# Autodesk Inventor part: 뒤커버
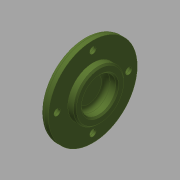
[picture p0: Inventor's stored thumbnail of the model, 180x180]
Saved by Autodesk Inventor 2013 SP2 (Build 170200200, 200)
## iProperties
Created: 2015-12
Part Number: 뒤커버
Document SubType Name: Modeling
Designer: mdu
Density: 2.71 g/cm^3
Material: 알루미늄 6061
Author: mdu
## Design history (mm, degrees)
sketch "스케치1"
  geometry: L1 (-7, 0)-(7, 0); L2 (-7, 0)-(-7, 15.539); L3 (-7, 15.539)-(-4, 18.5); L4 (-4, 18.5)-(-4, 31); L5 (-4, 31)-(2, 31); L6 (2, 31)-(2, 17.5); L7 (2, 17.5)-(7, 17.5); L8 (7, 17.5)-(7, 0); 2 further points
  constraints: 16 end point, 4 parallel, 2 perpendicular, 1 coincident, 1 horizontal, 1 midpoint
  dimensions: "d0" = 14 distance of L1.start L1.end; "d1" = 62 diameter of L5 L1; "d2" = 35 diameter of L7 L1; "d3" = 37 diameter of L3.end L1; "d4" = 3 distance between parallel lines of L4 L2; "d5" = 6 distance of L4.end L5.end
revolve "회전1" sketch "스케치1" stored, may be unused: angle "d6" = 90 deg
sketch "스케치2" dims "d32" = 50
  geometry: 3 further points
  constraints: 2 vertical alignment, 1 coincident, 2 other
hole "구멍1" sketch "스케치2" at (0, 25) diameter "d8" = 4.5; stored, may be unused: countersink angle "d12" = 90 deg, drill point angle "d14" = 118 deg; dims "d9" = 6, "d10" = 8, "d11" = 4.4, "d13" = 8
hole "구멍2" diameter "d20" = 24; stored, may be unused: countersink angle "d24" = 90 deg, drill point angle "d26" = 0 deg; dims "d18" = 10, "d19" = 10, "d21" = 6, "d22" = 8, "d23" = 4.4, "d25" = 8
fillet "모깎기1" dims "d27" = 3
fillet "모깎기2" dims "d28" = 3
chamfer "모따기1" distance "d29" = 1; stored, may be unused: second distance "d30" = 2, angle "d31" = 45 deg
node "솔리드1"
pattern_circular "원형 패턴1" dims angle "d16" = 360 deg
